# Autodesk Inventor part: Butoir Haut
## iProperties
Created: 2008-12
Part Number: Butoir Haut
Document SubType Name: Modeling
Designer: claivier
Author: claivier
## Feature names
1. Extrusion1
2. Extrusion2
3. Perçage1 [Hole]
